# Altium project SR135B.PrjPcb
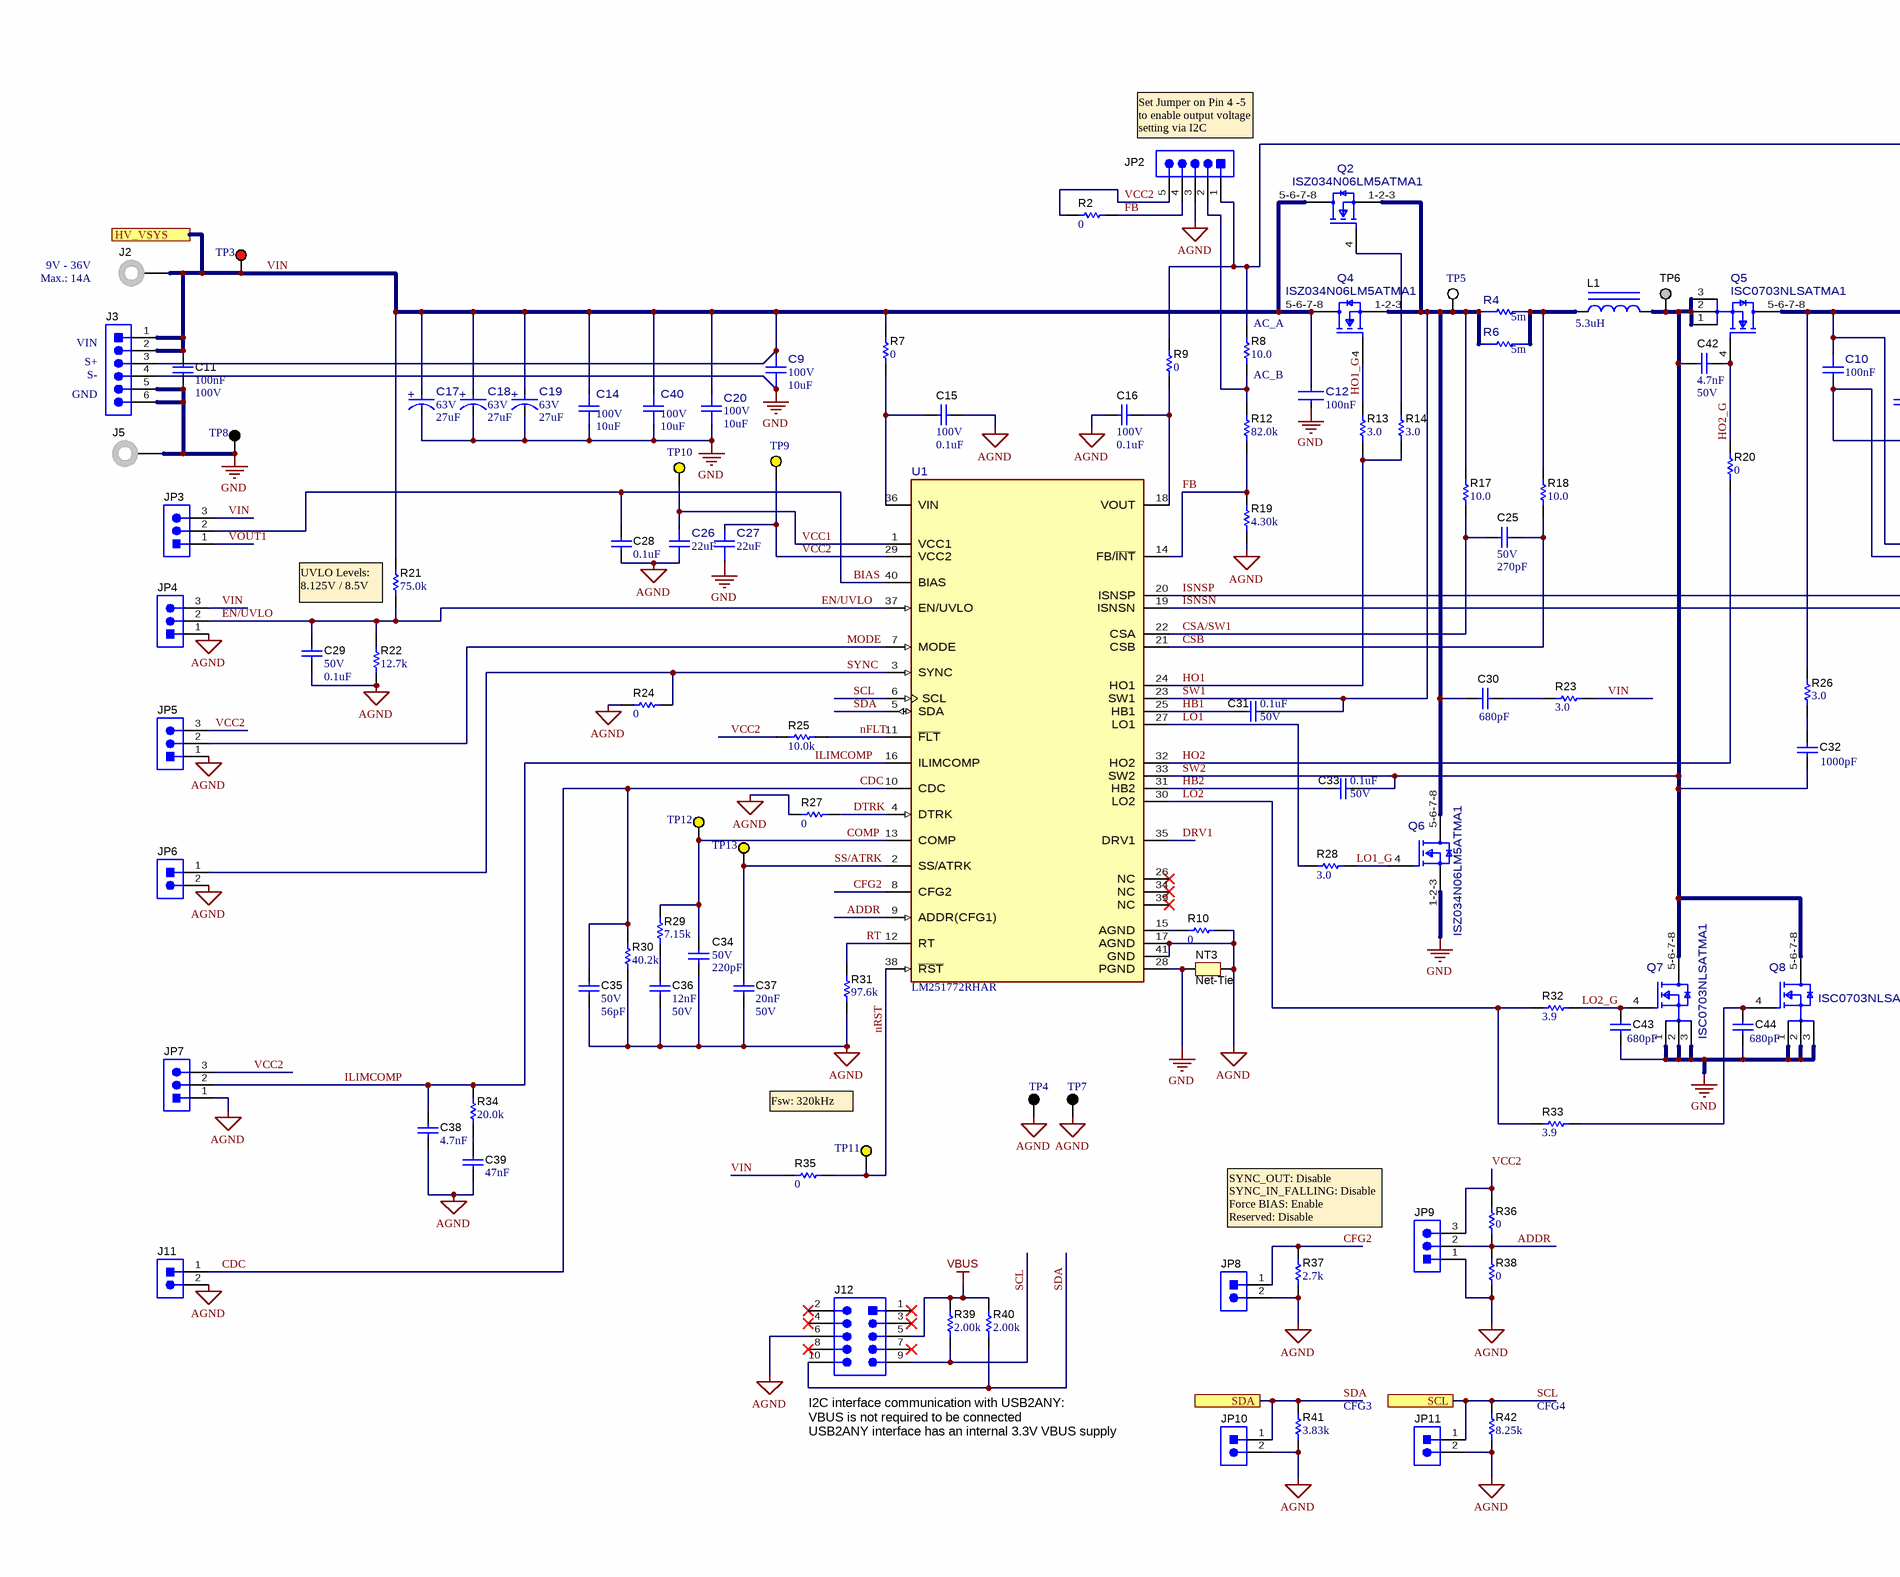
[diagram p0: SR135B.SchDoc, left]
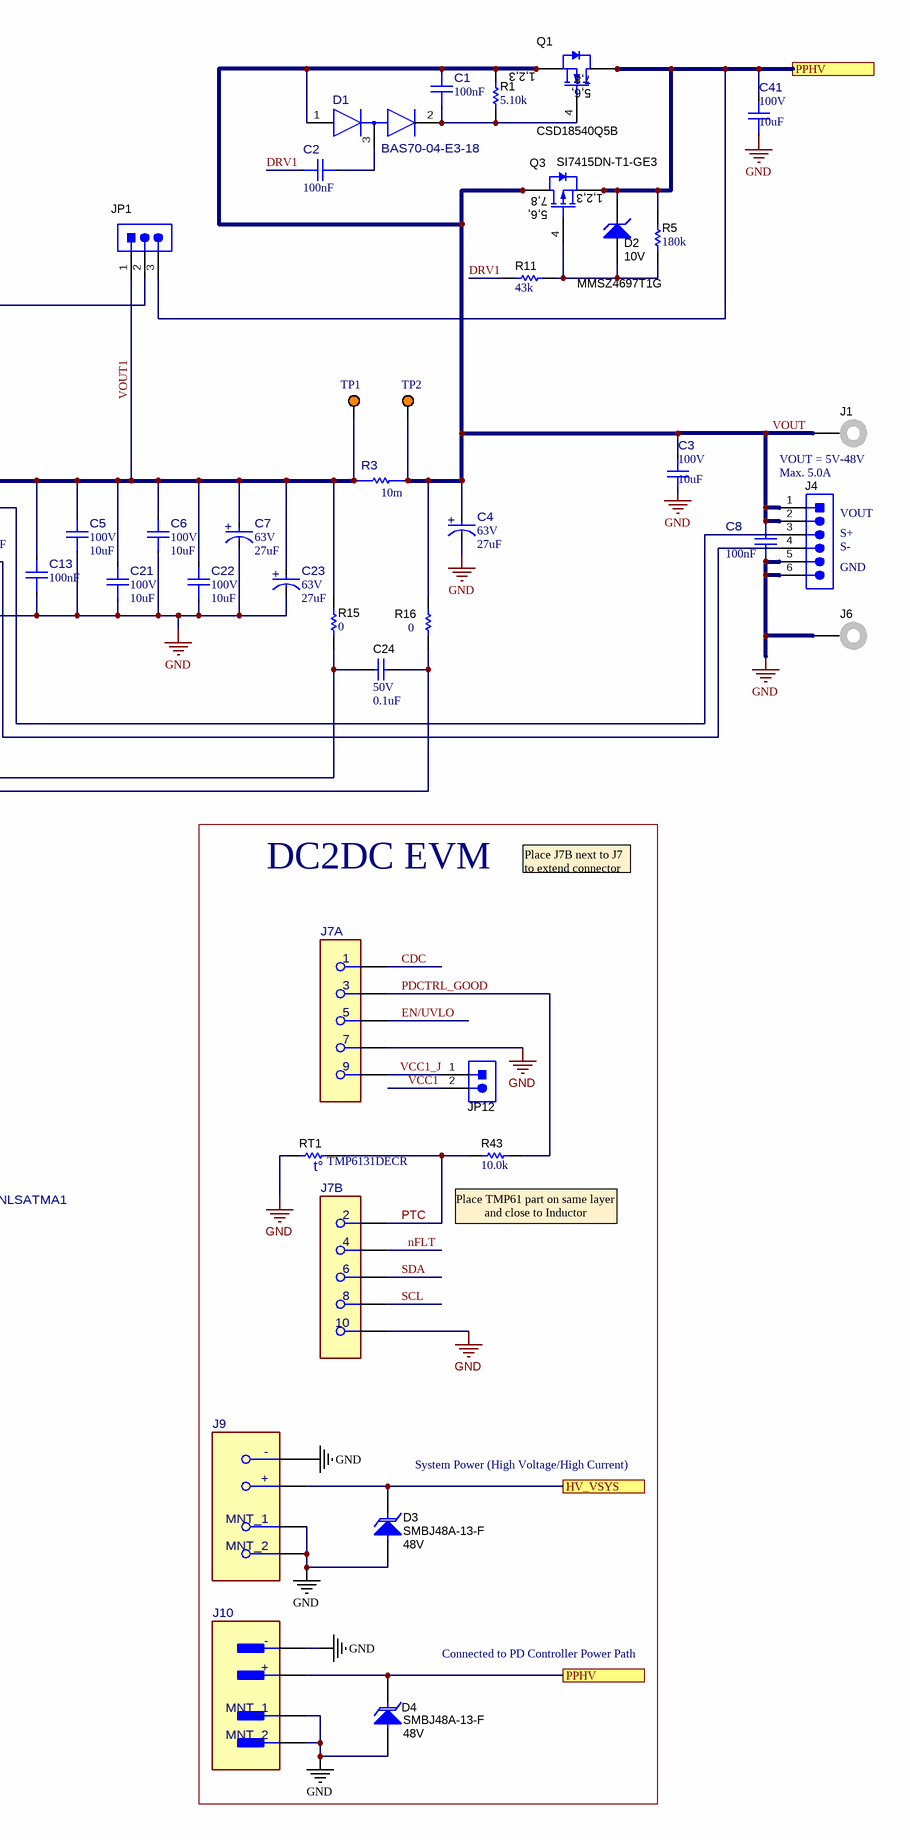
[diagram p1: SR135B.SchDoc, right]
TID: N/A; TechSupport: http://www.ti.com/support; SCH_Rev: B; PRJ_Title: LM251772EVM-PD; PRJ_Number: SR135; PRJ_Customer: Public Release; PCB_Rev: B; CopyrightYear: 2025
2 sheets, 170 parts. Net scope: flat (ports and power ports of the same name join across sheets).
Board file: SR135B.PcbDoc
Sheets:
  SR135B.SchDoc
  SR135B_Hardware.SchDoc

## Sheet SR135B.SchDoc
size 558 x 431 mm; Date: Not shown in title block; ApprovedBy: Not shown in title block; CheckedBy: Not shown in title block; Author: Not shown in title block; CompanyName: Not shown in title block; Engineer: Not shown in title block; Organization: Not shown in title block; Address1: Not shown in title block; Address2: Not shown in title block; Address3: Not shown in title block; Address4: Not shown in title block; DocumentNumber: 1; Revision: Use project parameter SCH_Rev; SheetNumber: 1; SheetTotal: 2; PageSetup: Record=PageOptions¦CenterHorizontal=True¦CenterVertical=True¦PrintScale=1.00¦XCorrection=1.00¦YCorrection=1.00¦PrintKind=0¦BorderSize=5000000¦LeftOffset=0¦BottomOffset=0¦Orientation=2¦PaperLength=1000¦PaperWidth=1000¦Scale=100¦PaperSource=15¦PrintQuality=600¦MediaType=1¦DitherType=10¦PaperKind=Letter¦PrintScaleMode=1

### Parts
C1  Cap_F: 100nF  [FP-GRM188R72A104KA35D_0603-MFG]  (hidden comment: GRM188R72A104KA35D)
C2  Cap_F: 100nF  [FP-GRM188R72A104KA35D_0603-MFG]  (hidden comment: GRM188R72A104KA35D)
C3  VDC_V: 100V  ValueDisplayed: 10uF  [FP-C3225X7R2A106K250AC_1210-MFG]  (hidden comment: C3225X7R2A106K250AC)
C4  VDC_V: 63V  ValueDisplayed: 27uF  [FP-A768KE276M1JLAE054_SMT_CAP_8MM3_8MM3-0]  (hidden comment: A768KE276M1JLAE054)
C5  VDC_V: 100V  ValueDisplayed: 10uF  [FP-C3225X7R2A106K250AC_1210-MFG]  (hidden comment: C3225X7R2A106K250AC)
C6  VDC_V: 100V  ValueDisplayed: 10uF  [FP-C3225X7R2A106K250AC_1210-MFG]  (hidden comment: C3225X7R2A106K250AC)
C7  VDC_V: 63V  ValueDisplayed: 27uF  [FP-A768KE276M1JLAE054_SMT_CAP_8MM3_8MM3-0]  (hidden comment: A768KE276M1JLAE054)
C8  Cap_F: 100nF  [FP-GRM188R72A104KA35D_0603-MFG]  (hidden comment: GRM188R72A104KA35D)
C9  VDC_V: 100V  ValueDisplayed: 10uF  [FP-C3225X7R2A106K250AC_1210-MFG]  (hidden comment: C3225X7R2A106K250AC)
C10  Cap_F: 100nF  [FP-GRM188R72A104KA35D_0603-MFG]  (hidden comment: GRM188R72A104KA35D)
C11  Cap_F: 100nF  VDC_V: 100V  [0603]  (hidden comment: GCJ188R72A104KA01D)
C12  Cap_F: 100nF  [FP-GCM188L81H104KA57D_0603-MFG]  (hidden comment: GCM188L81H104KA57D)
C13  Cap_F: 100nF  [FP-GRM188R72A104KA35D_0603-MFG]  (hidden comment: GRM188R72A104KA35D)
C14  VDC_V: 100V  ValueDisplayed: 10uF  [FP-C3225X7R2A106K250AC_1210-MFG]  (hidden comment: C3225X7R2A106K250AC)
C15  VDC_V: 100V  ValueDisplayed: 0.1uF  [0402S]  (hidden comment: GRM155R62A104KE14D)
C16  VDC_V: 100V  ValueDisplayed: 0.1uF  [0402S]  (hidden comment: GRM155R62A104KE14D)
C17  VDC_V: 63V  ValueDisplayed: 27uF  [FP-A768KE276M1JLAE054_SMT_CAP_8MM3_8MM3-0]  (hidden comment: A768KE276M1JLAE054)
C18  VDC_V: 63V  ValueDisplayed: 27uF  [FP-A768KE276M1JLAE054_SMT_CAP_8MM3_8MM3-0]  (hidden comment: A768KE276M1JLAE054)
C19  VDC_V: 63V  ValueDisplayed: 27uF  [FP-A768KE276M1JLAE054_SMT_CAP_8MM3_8MM3-0]  (hidden comment: A768KE276M1JLAE054)
C20  VDC_V: 100V  ValueDisplayed: 10uF  [FP-C3225X7R2A106K250AC_1210-MFG]  (hidden comment: C3225X7R2A106K250AC)
C21  VDC_V: 100V  ValueDisplayed: 10uF  [FP-C3225X7R2A106K250AC_1210-MFG]  (hidden comment: C3225X7R2A106K250AC)
C22  VDC_V: 100V  ValueDisplayed: 10uF  [FP-C3225X7R2A106K250AC_1210-MFG]  (hidden comment: C3225X7R2A106K250AC)
C23  VDC_V: 63V  ValueDisplayed: 27uF  [FP-A768KE276M1JLAE054_SMT_CAP_8MM3_8MM3-0]  (hidden comment: A768KE276M1JLAE054)
C24  VDC_V: 50V  ValueDisplayed: 0.1uF  [0402S]  (hidden comment: GRM155R71H104ME14D)
C25  VDC_V: 50V  ValueDisplayed: 270pF  [0402S]  (hidden comment: GRM1555C1H271JA01D)
C26  ValueDisplayed: 22uF  [0603S]  (hidden comment: GRT188R61A226ME13D)
C27  ValueDisplayed: 22uF  [0603S]  (hidden comment: GRT188R61A226ME13D)
C28  ValueDisplayed: 0.1uF  [0603S]  (hidden comment: CGA3E3X7S2A104K080AB)
C29  VDC_V: 50V  ValueDisplayed: 0.1uF  [0402S]  (hidden comment: GRM155R71H104ME14D)
C30  ValueDisplayed: 680pF  [0805_HV1]  (hidden comment: 08051A681JAT2A)
C31  VDC_V: 50V  ValueDisplayed: 0.1uF  [0402S]  (hidden comment: GCM155R71H104KE02D)
C32  ValueDisplayed: 1000pF  [0805_HV1]  (hidden comment: C0805C102J1GACTU)
C33  VDC_V: 50V  ValueDisplayed: 0.1uF  [0402S]  (hidden comment: GCM155R71H104KE02D)
C34  VDC_V: 50V  ValueDisplayed: 220pF  [0603S]  (hidden comment: 06035A221FAT2A)
C35  VDC_V: 50V  ValueDisplayed: 56pF  [0603S]  (hidden comment: 06035A560FAT2A)
C36  Cap_F: 12nF  VDC_V: 50V  [0603S]  (hidden comment: C0603C123K5RACTU)
C37  Cap_F: 20nF  VDC_V: 50V  [0603S]  (hidden comment: CC0603KRX7R9BB203)
C38  Cap_F: 4.7nF  [0603S]  (hidden comment: 06031C472JAT2A)
C39  Cap_F: 47nF  [0603S]  (hidden comment: 06035C473JAT2A)
C40  VDC_V: 100V  ValueDisplayed: 10uF  [FP-C3225X7R2A106K250AC_1210-MFG]  (hidden comment: C3225X7R2A106K250AC)
C41  VDC_V: 100V  ValueDisplayed: 10uF  [FP-C3225X7R2A106K250AC_1210-MFG]  (hidden comment: C3225X7R2A106K250AC)
C42  Cap_F: 4.7nF  VDC_V: 50V  [0603S]  (hidden comment: C0603C472K5RACTU)
C43  ValueDisplayed: 680pF  [0603S]  (hidden comment: C0603C681J5GACTU)
C44  ValueDisplayed: 680pF  [0603S]  (hidden comment: C0603C681J5GACTU)
D1  BAS70-04-E3-18  [FP-BAS70-04-E3-18_SOT23-3-MFG]
D2  MMSZ4697T1G  value 10V  [SOD-123]
D3  SMBJ48A-13-F  value 48V  [SMB]
D4  SMBJ48A-13-F  value 48V  [SMB]
J1  108-0740-001  [Johnson_108-0740-001]  (value not drawn)
J2  108-0740-001  [Johnson_108-0740-001]  (value not drawn)
J3  61300611121  [WURTH_61300611121]  (value not drawn)
J4  61300611121  [WURTH_61300611121]  (value not drawn)
J5  108-0740-001  [Johnson_108-0740-001]  (value not drawn)
J6  108-0740-001  [Johnson_108-0740-001]  (value not drawn)
J7  SSW-105-02-G-D-RA  [FP-SSW-105-02-G-D-RA_HDR10-MFG]  (value not drawn)  (parts A,B of 2)
J9  XT30PW-F  [FP-XT30PW-F_CONN_SOCKET_DC2-MFG]  (value not drawn)
J10  XT30PW-M  [FP-XT30PW-M_CONN_PLUG2-MFG]  (value not drawn)
J11  61300211121  [WURTH_61300211121]  (value not drawn)
J12  N2510-6002-RB  [CONN_2510-6002]  (value not drawn)
JP1  61300311121  [WURTH_61300311121]  (value not drawn)
JP2  61300511121  [Wurth_61300511121]  (value not drawn)
JP3  61300311121  [WURTH_61300311121]  (value not drawn)
JP4  61300311121  [WURTH_61300311121]  (value not drawn)
JP5  61300311121  [WURTH_61300311121]  (value not drawn)
JP6  61300211121  [WURTH_61300211121]  (value not drawn)
JP7  61300311121  [WURTH_61300311121]  (value not drawn)
JP8  61300211121  [WURTH_61300211121]  (value not drawn)
JP9  61300311121  [WURTH_61300311121]  (value not drawn)
JP10  61300211121  [WURTH_61300211121]  (value not drawn)
JP11  61300211121  [WURTH_61300211121]  (value not drawn)
JP12  61300211121  [WURTH_61300211121]  (value not drawn)
L1  ValueDisplayed: 5.3uH  [XAL1580]  (hidden comment: XAL1580-532MEB)
NT3  Net-Tie  [Net-Tie_10mil]  (net tie, no BOM)
Q1  CSD18540Q5B  [DNK0008A]
Q2  ISZ034N06LM5ATMA1  [FP-ISZ034N06LM5ATMA1_TSDSON8-MFG]
Q3  SI7415DN-T1-GE3  [PowerPAK_1212-8]
Q4  ISZ034N06LM5ATMA1  [FP-ISZ034N06LM5ATMA1_TSDSON8-MFG]
Q5  ISC0703NLSATMA1  [FP-ISC0702NLSATMA1_SuperSO8-5x6-MFG]
Q6  ISZ034N06LM5ATMA1  [FP-ISZ034N06LM5ATMA1_TSDSON8-MFG]
Q7  ISC0703NLSATMA1  [FP-ISC0702NLSATMA1_SuperSO8-5x6-MFG]
Q8  ISC0703NLSATMA1  [FP-ISC0702NLSATMA1_SuperSO8-5x6-MFG]
R1  ValueDisplayed: 5.10k  [0603S]  (hidden comment: RC0603FR-075K1L)
R2  ValueDisplayed: 0  [0603S]  (hidden comment: RMCF0603ZT0R00)
R3  value 10m  [FP-KRL2012E-C-R010-F-T05_0508-MFG]  (hidden comment: KRL2012E-C-R010-F-T05)
R4  value 5m  [FP-KRL2012E-M-R005-F-T5_0805_WIDE-MFG]  (hidden comment: KRL2012E-M-R005-F-T5)
R5  ValueDisplayed: 180k  [0603S]  (hidden comment: CRCW0603180KJNEA)
R6  value 5m  [FP-KRL2012E-M-R005-F-T5_0805_WIDE-MFG]  (hidden comment: KRL2012E-M-R005-F-T5)
R7  ValueDisplayed: 0  [0603S]  (hidden comment: RMCF0603ZT0R00)
R8  ValueDisplayed: 10.0  [0603S]  (hidden comment: RC0603FR-0710RL)
R9  ValueDisplayed: 0  [0603S]  (hidden comment: RMCF0603ZT0R00)
R10  ValueDisplayed: 0  [0603S]  (hidden comment: RMCF0603ZT0R00)
R11  ValueDisplayed: 43k  [0603S]  (hidden comment: CRCW060343K0JNEA)
R12  ValueDisplayed: 82.0k  [0603S]  (hidden comment: RC0603FR-0782KL)
R13  ValueDisplayed: 3.0  [0603S]  (hidden comment: CRCW06033R00JNEA)
R14  ValueDisplayed: 3.0  [0603S]  (hidden comment: CRCW06033R00JNEA)
R15  ValueDisplayed: 0  [0603S]  (hidden comment: RMCF0603ZT0R00)
R16  ValueDisplayed: 0  [0603S]  (hidden comment: RMCF0603ZT0R00)
R17  ValueDisplayed: 10.0  [0603S]  (hidden comment: CRCW060310R0FKEAHP)
R18  ValueDisplayed: 10.0  [0603S]  (hidden comment: CRCW060310R0FKEAHP)
R19  ValueDisplayed: 4.30k  [0603S]  (hidden comment: RC0603FR-074K3L)
R20  ValueDisplayed: 0  [0603S]  (hidden comment: RMCF0603ZT0R00)
R21  ValueDisplayed: 75.0k  [0603S]  (hidden comment: RC0603FR-0775KL)
R22  ValueDisplayed: 12.7k  [0603S]  (hidden comment: RC0603FR-0712K7L)
R23  ValueDisplayed: 3.0  [1206L]  (hidden comment: CRCW12063R00JNEA)
R24  ValueDisplayed: 0  [0603S]  (hidden comment: RMCF0603ZT0R00)
R25  ValueDisplayed: 10.0k  [0603S]  (hidden comment: RT0603BRD0710KL)
R26  ValueDisplayed: 3.0  [1206L]  (hidden comment: CRCW12063R00JNEA)
R27  ValueDisplayed: 0  [0603S]  (hidden comment: RMCF0603ZT0R00)
R28  ValueDisplayed: 3.0  [0603S]  (hidden comment: CRCW06033R00JNEA)
R29  ValueDisplayed: 7.15k  [0603S]  (hidden comment: CRCW06037K15FKEA)
R30  ValueDisplayed: 40.2k  [0603S]  (hidden comment: CRCW060340K2FKEA)
R31  ValueDisplayed: 97.6k  [0603S]  (hidden comment: RC0603FR-0797K6L)
R32  ValueDisplayed: 3.9  [0603S]  (hidden comment: CRCW06033R90JNEA)
R33  ValueDisplayed: 3.9  [0603S]  (hidden comment: CRCW06033R90JNEA)
R34  ValueDisplayed: 20.0k  [0603S]  (hidden comment: CRCW060320K0FKEA)
R35  ValueDisplayed: 0  [0603S]  (hidden comment: RMCF0603ZT0R00)
R36  ValueDisplayed: 0  [0603S]  (hidden comment: RMCF0603ZT0R00)
R37  ValueDisplayed: 2.7k  [0603S]  (hidden comment: CRCW06032K70JNEA)
R38  ValueDisplayed: 0  [0603S]  (hidden comment: RMCF0603ZT0R00)
R39  ValueDisplayed: 2.00k  [0603S]  (hidden comment: RC0603FR-072KL)
R40  ValueDisplayed: 2.00k  [0603S]  (hidden comment: RC0603FR-072KL)
R41  ValueDisplayed: 3.83k  [0603S]  (hidden comment: CRCW06033K83FKEA)
R42  ValueDisplayed: 8.25k  [0603S]  (hidden comment: RC0603FR-078K25L)
R43  ValueDisplayed: 10.0k  [TNPW0603]  (hidden comment: TNPW060310K0BEEA)
RT1  TMP6131DECR  [DEC0002A-MFG]
TP1  5013  [Keystone5013]  (value not drawn)
TP2  5013  [Keystone5013]  (value not drawn)
TP3  5010  [Keystone5010]  (value not drawn)
TP4  5001  [Keystone5001]  (value not drawn)
TP5  5012  [Keystone5012]  (value not drawn)
TP6  5128  [Keystone5128]  (value not drawn)
TP7  5001  [Keystone5001]  (value not drawn)
TP8  5011  [Keystone5011]  (value not drawn)
TP9  5004  [Keystone5004]  (value not drawn)
TP10  5004  [Keystone5004]  (value not drawn)
TP11  5004  [Keystone5004]  (value not drawn)
TP12  5004  [Keystone5004]  (value not drawn)
TP13  5004  [Keystone5004]  (value not drawn)
U1  LM251772RHAR  [RHA0040P-MFG]

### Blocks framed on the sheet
DC2DC EVM: D3 D4 J7 J9 J10 JP12 R43 RT1

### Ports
HV_VSYS, PPHV, SCL, SDA

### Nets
AGND: C15.1 C16.2 C26.1 C28.1 C29.2 C34.2 C35.2 C36.2 C37.2 C38.2 C39.2 J11.2 J12.6 JP2.3 JP4.1 JP5.1 JP6.2 JP7.1 JP8.2 JP9.1 JP10.2 JP11.2 NT3.2 R10.1 R19.1 R22.1 R24.1 R27.1 R30.1 R31.1 R37.1 R38.2 R41.1 R42.1 TP4.1 TP7.1 U1.17(AGND) U1.41(GND)
GND: C3.1 C4.1(CATHODE) C5.1 C6.1 C7.1(CATHODE) C8.1 C9.1 C10.1 C11.2 C12.2 C13.1 C14.1 C17.1(CATHODE) C18.1(CATHODE) C19.1(CATHODE) C20.1 C21.1 C22.1 C23.1(CATHODE) C27.1 C40.1 C41.1 C43.2 C44.2 D3.2(A) D4.2(A) J3.4 J3.5 J3.6 J4.4 J4.5 J4.6 J5.1 J6.1 J7.7 J7.10 J9.1(-) J9.3(MNT_1) J9.4(MNT_2) J10.1(-) J10.3(MNT_1) J10.4(MNT_2) NT3.1 Q6.1-2-3(S) Q7.1(Source) Q7.2(Source) Q7.3(Source) Q8.1(Source) Q8.2(Source) Q8.3(Source) RT1.1 TP8.1 U1.28(PGND)
VBUS: J12.5 R39.2 R40.2
ADDR: JP9.2 R36.2 R38.1 U1.9(ADDR(CFG1))
BIAS: C28.2 JP3.2 U1.40(BIAS)
CDC: C35.1 J7.1 J11.1 R30.2 U1.10(CDC)
CFG2: JP8.1 R37.2 U1.8(CFG2)
COMP: C34.1 R29.2 TP12.1 U1.13(COMP)
CSA/SW1: C25.2 R17.1 U1.22(CSA)
CSB: C25.1 R18.1 U1.21(CSB)
DRV1: C2.1 R11.1 U1.35(DRV1)
DTRK: R27.2 U1.4(DTRK)
EN/UVLO: C29.1 J7.5 JP4.2 R21.1 R22.2 U1.37(EN/UVLO)
FB: JP2.4 R2.1 R12.1 R19.2 U1.14(FB/~{INT})
HB1: C31.2 U1.25(HB1)
HB2: C33.2 U1.31(HB2)
HO1: R13.1 R14.1 U1.24(HO1)
HO1_G: Q4.4(G) R13.2
HO2: R20.1 U1.32(HO2)
HO2_G: C42.2 Q5.4(Gate) R20.2
ILIMCOMP: C38.1 JP7.2 R34.2 U1.16(ILIMCOMP)
ISNSN: C24.1 R16.1 U1.19(ISNSN)
ISNSP: C24.2 R15.1 U1.20(ISNSP)
LO1: R28.2 U1.27(LO1)
LO1_G: Q6.4(G) R28.1
LO2: R32.1 R33.1 U1.30(LO2)
LO2_G: C43.1 Q7.4(Gate) R32.2
MODE: JP5.2 U1.7(MODE)
nFLT: J7.4 R25.1 U1.11(~{FLT})
nRST: R35.1 TP11.1 U1.38(~{RST})
PDCTRL_GOOD: J7.3 R43.1
PPHV: C41.2 D2.1(K) D4.1(K) J10.2(+) JP1.3 Q1.5(D) Q1.6(D) Q1.7(D) Q1.8(D) Q1.9(D) Q3.1(S) Q3.2(S) Q3.3(S) R5.2 ; port PPHV
PTC: J7.2 R43.2 RT1.2
RT: R31.2 U1.12(RT)
SCL: J7.8 J12.9 JP11.1 R39.1 R42.2 U1.6(SCL) ; port SCL
SDA: J7.6 J12.10 JP10.1 R40.1 R41.2 U1.5(SDA) ; port SDA
SS/ATRK: C37.1 TP13.1 U1.2(SS/ATRK)
SW1: C30.2 C31.1 Q2.1-2-3(S) Q4.1-2-3(S) Q6.5-6-7-8(D) R4.2 R6.2 R17.2 TP5.1 U1.23(SW1)
SW2: C32.2 C33.1 C42.1 L1.2 Q5.1(Source) Q5.2(Source) Q5.3(Source) Q7.5-6-7-8(Drain) Q8.5-6-7-8(Drain) TP6.1 U1.33(SW2)
SYNC: JP6.1 R24.2 U1.3(SYNC)
VCC1: C26.2 JP12.2 TP10.1 U1.1(VCC1)
VCC1_J: J7.9 JP12.1
VCC2: C27.2 JP2.5 JP5.3 JP7.3 JP9.3 R2.2 R25.2 R36.1 TP9.1 U1.29(VCC2)
VIN: C9.2 C11.1 C12.1 C14.2 C17.2(ANODE) C18.2(ANODE) C19.2(ANODE) C20.2 C40.2 D3.1(K) J2.1 J3.1 J3.2 J3.3 J9.2(+) JP3.3 JP4.3 Q2.5-6-7-8(D) Q4.5-6-7-8(D) R7.2 R21.2 R23.2 R35.2 TP3.1 ; port HV_VSYS
VOUT: C1.2 C3.2 C4.2(ANODE) C8.2 D1.1(1_ANODE) J1.1 J4.1 J4.2 Q1.1(S) Q1.2(S) Q1.3(S) Q3.5(D) Q3.6(D) Q3.7(D) Q3.8(D) Q3.9(D) R1.2 R3.2 R16.2 TP2.1
VOUT1: C5.2 C6.2 C7.2(ANODE) C10.2 C13.2 C21.2 C22.2 C23.2(ANODE) J4.3 JP1.1 JP3.1 Q5.5-6-7-8(Drain) R3.1 R15.2 R26.2 TP1.1
NetC1_1: C1.1 D1.2(2_CATHODE) Q1.4(G) R1.1
NetC2_2: C2.2 D1.3(1_CATHODE/2_ANODE)
NetC15_2: C15.2 R7.1 U1.36(VIN)
NetC16_1: C16.1 R9.1 U1.18(VOUT)
NetC30_1: C30.1 R23.1
NetC32_1: C32.1 R26.1
NetC36_1: C36.1 R29.1
NetC39_1: C39.1 R34.1
NetC44_1: C44.1 Q8.4(Gate) R33.2
NetD2_2: D2.2(A) Q3.4(G) R5.1 R11.2
NetJP1_2: JP1.2 JP2.1 R8.2 R9.2
NetJP2_2: JP2.2 R8.1 R12.2
NetL1_1: L1.1 R4.1 R6.1 R18.2
NetQ2_4: Q2.4(G) R14.2
NetR10_2: R10.2 U1.15(AGND)

Not connected (* = marked no-connect by the designer): J12 1* 2* 3* 4* 7* 8*; U1 26(NC)* 34(NC)* 39(NC)*

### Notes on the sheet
- (near JP2) Set Jumper on Pin 4 -5 to enable output voltage setting via I2C
- 9V - 36V
- Max.: 14A
- (near J3) VIN
- (near R8) AC_A
- (near J1) VOUT = 5V-48V
- Max. 5.0A
- (near J4) VOUT
- (near J3) S+
- (near J3) S-
- (near J3) GND
- (near R8) AC_B
- (near J4) S+
- (near J4) S-
- (near J4) GND
- (near R21) UVLO Levels:
  8.125V / 8.5V
- Place J7B next to J7 to extend connector
- (near R43) Place TMP61 part on same layer and close to Inductor
- Fsw: 320kHz
- (near R37) SYNC_OUT: Disable
  SYNC_IN_FALLING: Disable
  Force BIAS: Enable
  Reserved: Disable
- (near D3) System Power (High Voltage/High Current)
- (near R41) CFG3
- (near R42) CFG4
- Connected to PD Controller Power Path
- (near J12) I2C interface communication with USB2ANY:
  VBUS is not required to be connected
  USB2ANY interface has an internal 3.3V VBUS supply

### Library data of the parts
C1 C2 C8 C10 C13 = CMP-0088837-1: 0.1µF ±10% 100V Ceramic Capacitor X7R 0603 (1608 Metric); Manufacturer: Murata; AEC Qualified: No; Import Ts: 1521862704; TempCo: 15%; Ciiva Ids: 120189; ValueDisplayed: 0.1uF; SizeZ_mm: 0.9mm
C3 C5 C6 C9 C14 C20-C22 C40 C41 = CMP-0096021-1: 10 µF ±10% 100V Ceramic Capacitor X7R 1210 (3225 Metric); Manufacturer: TDK; Cap_F: 10µF; AEC Qualified: No; Value: 10µF; SizeZ_mm: 2.85mm; TempCo: 15%
C4 C7 C17-C19 C23 = CMP-0097690-1: Cap Aluminum Polymer 27uF 63V 20% Solder Cylindrical 54m Ohm 1175mA 2000 hr 125°C T/R; Manufacturer: KEMET; Life: 2000Hours; Cap_F: 27µF; Value: 27µF; Leakage Current: 340uA; SizeZ_mm: 7mm; IRMS_A: 1.175A; AEC Qualified: No
C11 = CMP-0064935-4: CAP, CERM, 0.1 uF, 100 V,+/- 10%, X7R, AEC-Q200 Grade 1, 0603; Manufacturer: MuRata; TaMin_C: -55°C; Polarized: N; SizeAreaWB_mm2: 4.68; Value1: Unknown; U/M: EA; Value: 0.1uF; TaMax_C: 125°C; SizeZ_mm: 1; SizeX_mm: 1.6; SizeY_mm: 0.8; SizeArea_mm2: 1.28; AEC Qualified: Y; AEC Category: Q200
C12 = CMP-0086535-1: 0.1µF ±10% 50V Ceramic Capacitor X8L 0603 (1608 Metric); Manufacturer: Murata Electronics North America; Symbol Name: SYM-GCM188L81H104KA57D; AEC Qualified: Yes; TempCo: -40+15%; SizeZ_mm: 0.9mm; AEC Grade: Grade 0
C15 C16 = CMP-0006618-2: CAP, CERM, 0.1 uF, 100 V, +/- 10%, X5R, 0402; Manufacturer: MuRata; TaMin_C: -55°C; Polarized: N; SizeAreaWB_mm2: 3; Value1: Unknown; U/M: EA; Value: 0.1uF; TaMax_C: 85°C; SizeZ_mm: 0.6; SizeX_mm: 1; SizeY_mm: 0.5; Cap_Case: 0402; Cap_F: 100nF; AEC Category: Q200
C24 C29 = CMP-0006675-2: CAP, CERM, 0.1 uF, 50 V, +/- 20%, X7R, 0402; Manufacturer: MuRata; TaMin_C: -55°C; Polarized: N; SizeAreaWB_mm2: 3; Value1: Unknown; U/M: EA; Value: 0.1uF; TaMax_C: 125°C; SizeZ_mm: 0.6; SizeX_mm: 1; SizeY_mm: 0.5; Cap_Case: 0402; Cap_F: 100nF; AEC Category: Q200
C25 = CMP-0006445-2: CAP, CERM, 270 pF, 50 V, +/- 5%, C0G/NP0, 0402; Manufacturer: MuRata; TaMin_C: -55°C; Polarized: N; SizeAreaWB_mm2: 3; Value1: Unknown; U/M: EA; Value: 270pF; TaMax_C: 125°C; SizeZ_mm: 0.6; SizeX_mm: 1; SizeY_mm: 0.5; Cap_Case: 0402; AEC Category: Q200
C26 C27 = CMP-0092433-2: Multi-Layer Ceramic Capacitor 22uF 10V X5R ±20% 0603 Paper T/R; Manufacturer: Murata; Cap_F: 22µF; Value: 22µF; SizeZ_mm: 1mm; AEC Qualified: Yes; AEC Grade: Grade 3; TempCo: 15%
C28 = CMP-0007099-4: CAP, CERM, 0.1 uF, 100 V, +/- 10%, X7S, AEC-Q200 Grade 1, 0603; Manufacturer: TDK; TaMin_C: -55°C; ESR_ohm: 0.04959; Polarized: N; SizeAreaWB_mm2: 4.68; Value1: 0.04959 ohm; U/M: EA; Value: 0.1uF; TaMax_C: 125°C; SizeZ_mm: 1; SizeX_mm: 1.6; SizeY_mm: 0.8; Cap_Case: 0603; Value2: 100V; SizeArea_mm2: 1.28; AEC Qualified: Y; Cap_F: 100nF; IRMS_A: 7.51618dA; AEC Category: Q200
C30 = CMP-0007537-2: CAP, CERM, 680 pF, 100 V, +/- 5%, C0G/NP0, 0805; Manufacturer: AVX; TaMin_C: -55°C; ESR_ohm: 1.34d; Polarized: N; SizeAreaWB_mm2: 6.75; Value1: 0.134 ohm; U/M: EA; Value: 680pF; TaMax_C: 125°C; SizeZ_mm: 1.45; SizeX_mm: 2; SizeY_mm: 1.25; Cap_Case: 0805; Value2: 100V; SizeArea_mm2: 2.5; AEC Category: Q200
C31 C33 = CMP-0006356-2: CAP, CERM, 0.1 uF, 50 V, +/- 10%, X7R, AEC-Q200 Grade 1, 0402; Manufacturer: MuRata; TaMin_C: -55°C; Polarized: N; SizeAreaWB_mm2: 3; Value1: Unknown; U/M: EA; Value: 0.1uF; TaMax_C: 125°C; SizeZ_mm: 0.6; SizeX_mm: 1; SizeY_mm: 0.5; Cap_Case: 0402; AEC Qualified: Y; Cap_F: 100nF; AEC Category: Q200
C32 = CMP-0007709-2: CAP, CERM, 1000 pF, 100 V, +/- 5%, C0G/NP0, 0805; Manufacturer: Kemet; TaMin_C: -55°C; ESR_ohm: 0.025; Polarized: N; SizeAreaWB_mm2: 6.75; Value1: 0.025 ohm; U/M: EA; Value: 1000pF; TaMax_C: 125°C; SizeZ_mm: 1.45; SizeX_mm: 2; SizeY_mm: 1.25; Cap_Case: 0805; Value2: 100V; SizeArea_mm2: 2.5; Cap_F: 1nF; IRMS_A: 1.71A; AEC Category: Q200
C34 = CMP-0006776-4: CAP, CERM, 220 pF, 50 V, +/- 1%, C0G/NP0, 0603; Manufacturer: AVX; TaMin_C: -55°C; ESR_ohm: 83m; Polarized: N; SizeAreaWB_mm2: 4.68; Value1: 0.083 ohm; U/M: EA; Value: 220pF; TaMax_C: 125°C; SizeZ_mm: 1; SizeX_mm: 1.6; SizeY_mm: 0.8; Cap_Case: 0603; SizeArea_mm2: 1.28; AEC Category: Q200
C35 = CMP-0006792-4: CAP, CERM, 56 pF, 50 V, +/- 1%, C0G/NP0, 0603; Manufacturer: AVX; TaMin_C: -55°C; Polarized: N; SizeAreaWB_mm2: 4.68; Value1: Unknown; U/M: EA; Value: 56pF; TaMax_C: 125°C; SizeZ_mm: 1; SizeX_mm: 1.6; SizeY_mm: 0.8; Cap_Case: 0603; SizeArea_mm2: 1.28; AEC Category: Q200
C36 = CMP-0084236-1: CAP, CERM, 0.012 µF, 50 V,+/- 10%, X7R, AEC-Q200 Grade 1, 0603; Manufacturer: Kemet; TaMin_C: -55°C; Polarized: N; SizeAreaWB_mm2: 4.68; U/M: EA; Value: 0.012uF; TaMax_C: 125°C; SizeZ_mm: 1; SizeX_mm: 1.6; SizeY_mm: 0.8; Cap_Case: 0603; SizeArea_mm2: 1.28; AEC Qualified: Y; AEC Category: Q200
C37 = CMP-0086295-1: CAP, CERM, 0.02 µF, 50 V,+/- 10%, X7R, 0603; Manufacturer: Yageo; SizeX_mm: 1.6; SizeAreaWB_mm2: 4.68; TaMin_C: -55°C; SizeZ_mm: 1; SizeArea_mm2: 1.28; U/M: EA; Value: 0.02uF; Polarized: N; SizeY_mm: 0.8; TaMax_C: 125°C; Cap_Case: 0603; AEC Category: Q200; ValueDisplayed: 0.02µF
C38 = CMP-0006745-4: CAP, CERM, 4700 pF, 100 V, +/- 5%, X7R, 0603; Manufacturer: AVX; TaMin_C: -55°C; ESR_ohm: 1.36d; Polarized: N; SizeAreaWB_mm2: 4.68; Value1: 0.136 ohm; U/M: EA; Value: 4700pF; TaMax_C: 125°C; SizeZ_mm: 1; SizeX_mm: 1.6; SizeY_mm: 0.8; Cap_Case: 0603; Value2: 100V; SizeArea_mm2: 1.28; AEC Category: Q200
C39 = CMP-0085252-1: CAP, CERM, 0.047 µF, 50 V,+/- 5%, X7R, 0603; Manufacturer: AVX; VDC_V: 50V; TaMax_C: 125°C; Value: 0.047uF; SizeX_mm: 1.6; SizeArea_mm2: 1.28; AEC Category: Q200; SizeY_mm: 0.8; Polarized: N; Cap_Case: 0603; SizeAreaWB_mm2: 4.68; U/M: EA; TaMin_C: -55°C; SizeZ_mm: 1
C42 = CMP-0006943-4: CAP, CERM, 4700 pF, 50 V, +/- 10%, X7R, 0603; Manufacturer: Kemet; TaMin_C: -55°C; Polarized: N; SizeAreaWB_mm2: 4.68; Value1: Unknown; U/M: EA; Value: 4700pF; TaMax_C: 125°C; SizeZ_mm: 1; SizeX_mm: 1.6; SizeY_mm: 0.8; Cap_Case: 0603; SizeArea_mm2: 1.28; AEC Category: Q200
C43 C44 = CMP-0006959-4: CAP, CERM, 680 pF, 50 V, +/- 5%, C0G/NP0, 0603; Manufacturer: Kemet; TaMin_C: -55°C; Polarized: N; SizeAreaWB_mm2: 4.68; Value1: Unknown; U/M: EA; Value: 680pF; TaMax_C: 125°C; SizeZ_mm: 1; SizeX_mm: 1.6; SizeY_mm: 0.8; Cap_Case: 0603; Value2: 50V; SizeArea_mm2: 1.28; AEC Category: Q200
D1 = CMP-0096356-1: Diode Array 1 Pair Series Connection Schottky 70 V 200mA (DC) Surface Mount TO-236-3, SC-59, SOT-23-3; Manufacturer: Vishay; ValueDisplayed: 1.5pF; Vf_V: 70V; TJmax_C: 125°C; AEC Qualified: No; Peak Reverse Current: 0.02uA; SizeZ_mm: 1.15mm; Max Surge Forward Current: 600mA
D2 = CMP-0005740-3: Diode, Zener, 10 V, 500 mW, SOD-123; Manufacturer: ON Semiconductor; SizeY_mm: 1.7; SizeX_mm: 3.85; RJA_CperW: 340; SizeAreaWB_mm2: 13.095; AEC Category: Q101; Power_W: 500mW; SizeZ_mm: 1.35; Value1: 0.5W; SizeArea_mm2: 6.545
D3 D4 = CMP-0005570-3: Diode, TVS, Uni, 48 V, 77.4 Vc, SMB; Manufacturer: Diodes Inc.; Vbr_Min: 53.3V; AEC Category: Q101; Vbr_Max: 61.3V; Ppk: 600W; SizeZ_mm: 2.6; Ipp: 7.7A; SizeY_mm: 3.81; Vc: 77.4V; SizeAreaWB_mm2: 44.156; SizeX_mm: 5.6; SizeArea_mm2: 21.336
J1 J2 J5 J6 = CMP-0055387-2: Standard Banana Jack, Uninsulated, 15A; Manufacturer: Cinch Connectivity; CNHeader: FALSE; Green_Lifecycle: Active; Green_REACh: Passed; CT: TRUE
J3 J4 = CMP-0054801-2: Header, 2.54 mm, 6x1, Gold, TH; Manufacturer: Wurth Elektronik; Cert_UL: Y; Gender: Male; Row_Count: 1; Shrouded: N; Pitch_mm: 2.54
J7 = CMP-0120964-1: 10 Position Receptacle Connector 0.100" (2.54mm) Through Hole, Right Angle Gold; Manufacturer: Samtec; ContactFinish: Gold,Nickel; Current_A: 4.7A; Row_Count: 2; Voltage_V: 655V; AEC Qualified: No; Ciiva Ids: 678828; Conn Gender: Female; Import Ts: 1521843394; Is Female: yes; SizeZ_mm: 5.08mm
J9 = CMP-0035193-3: Socket, DC supply, XT30, female, PIN: 2, on PCBs, THT, yellow, 15A; Manufacturer: Amass; ContactFinish: Gold; Voltage_V: 500V; AEC Qualified: No; Conn Orientation: Right Angle; DUT-Pitch_mm: 5mm; Is Female: yes; Standoff Height: 0.1mm
J10 = CMP-0121007-1: Socket, DC supply, XT30, male, PIN: 2, on PCBs, THT, yellow, 15A, 500V; Manufacturer: Amass; ContactFinish: Gold; AEC Qualified: No; Conn Orientation: Right Angle; DUT-Pitch_mm: 5mm; SizeZ_mm: 5.1mm; Standoff Height: 0.1mm
J11 JP6 JP8 JP10-JP12 = CMP-0054794-2: Header, 2.54 mm, 2x1, Gold, TH; Manufacturer: Wurth Elektronik; Shrouded: N; Gender: Male; Green_REACh: Passed; Pitch_mm: 2.54; Green_Lifecycle: Active; Row_Count: 1; Cert_UL: Y
J12 = CMP-0055448-2: Header (shrouded), 100mil, 5x2, High-Temperature, Gold, TH; Manufacturer: 3M; Green_Lifecycle: Active; Green_REACh: Passed
JP1 JP3-JP5 JP7 JP9 = CMP-0054796-4: Header, 2.54 mm, 3x1, Gold, TH; Manufacturer: Wurth Elektronik; Green_Lifecycle: Active; Green_REACh: Passed; CT: FALSE; CNHeader: TRUE
JP2 = CMP-0084909-1: Header, 2.54mm, 5x1, Gold, TH; Manufacturer: Wurth Elektronik; Pitch_mm: 2.54; Current_A: 3A; Shrouded: N; Gender: Male; Voltage_V: 250V; Row_Count: 1
L1 = CMP-0060980-1: Inductor, Shielded, Composite, 5.3 uH, 26.5 A, 0.00435 ohm, SMD; Manufacturer: Coilcraft; Isat: 33A @ 0.7% inductance drop; Irms: 26.5A @ 40C rise; Green_Lifecycle: Not Set; SizeAreaWB_mm2: 313.04; DCR_ohm: 4.35m; Green_REACh: Incomplete; Value: 5.3uH; Imax_A: 26.5A; SizeZ_mm: 8; SizeX_mm: 15.2; SizeY_mm: 16.2; SizeArea_mm2: 246.24; Ind_H: 5.3µH; AEC Category: Q200
NT3 = CMP-0078142-6: Single point connection between nets.
Q1 = CMP-0000823-2: MOSFET, N-CH, 60 V, 100 A, DNK0008A (VSON-CLIP-8); Alternate Manufacturer: None; Manufacturer: Texas Instruments; SizeZ_mm: 1; ChType: N; Value2: 41 nC; Value1: 0.003; VdsMax_V: 60V; SizeX_mm: 6; SizeY_mm: 5; Vgs_V: 20V; Value: 60V; Rdson45_ohm: 3.3m; SizeArea_mm2: 30; AEC Category: Q101; IdsMax_A: 100A; SizeAreaWB_mm2: 56; U/M: EA; QgTyp_nC: 41
Q2 Q4 Q6 = CMP-0097450-1: N-Channel 60 V 19A (Ta), 112A (Tc) 2.5W (Ta), 83W (Tc) Surface Mount PG-TSDSON-8-26; Manufacturer: Infineon; Reverse Recovery Time: 20ns; Turn Off Delay Time: 27ns; Vgs_V: 20V; Threshold Vgs Min: 1.1V; TJmax_C: +175°C; Turn On Delay Time: 7.6ns; VdsMax_V: 1V; Pulse Drain Current: 448A; Rdson45_ohm: 2.9m; QgTyp_nC: 40nC @ 10V; Typ Forward Diode Voltage: 0.81V; Reverse Recovery Charge: 50nC; Rthja Max: 60°C/W; SizeZ_mm: 1mm; Transconductance: 80S; Threshold Vgs Max: 2.3V; Number Of Channels: 1; Input Capacitace At Vds: 2600pF @ 30V; AEC Qualified: No; Drain To Source Breakdown Voltage: 60V; ChMode: False
Q3 = CMP-0000115-4: MOSFET, P-CH, -60 V, -3.6 A, PowerPAK 1212; Manufacturer: Vishay-Siliconix; Alternate Manufacturer: None; IdsMax_A: -3.6A; ChType: P; Vgs_V: -20V; Value1: 0.1; QgTyp_nC: 15; VdsMax_V: -60V; SizeAreaWB_mm2: 18.49; SizeX_mm: 3.3; ChMode: Enhancement; SizeArea_mm2: 10.89; Value: -60V; AEC Category: Q101; SizeZ_mm: 1.04; Rdson45_ohm: 0.11; Value2: 15 nC
Q5 Q7 Q8 = CMP-0097724-1: MOSFET N-Channel 60 V 23A (Ta), 135A (Tc) 3W (Ta), 100W (Tc) Surface Mount PG-TDSON-8; Manufacturer: Infineon; QgTyp_nC: 42nC @ 10V; VdsMax_V: 1.1V; Turn Off Delay Time: 7.5ns; Transconductance: 130S; SizeZ_mm: 1mm; Turn On Delay Time: 6.5ns; Drain To Source Breakdown Voltage: 60V; Reverse Recovery Time: 43ns; Number Of N Channels: 1; Pulse Drain Current: 540A; TJmax_C: +175°C; Rthja Max: 50°C/W; Vgs_V: 20V; Typ Forward Diode Voltage: 0.85V; Threshold Vgs Max: 2.3V; Reverse Recovery Charge: 49nC; ChMode: False; Rdson45_ohm: 3m; Input Capacitace At Vds: 2700pF @ 30V; AEC Qualified: No
R1 = CMP-0023198-5: RES, 5.10 k, 1%, 0.1 W, 0603; Manufacturer: Yageo; Power_W: 100mW; TempCo: 100 ppm/C; Value_Code: 5k10; Value: 5.10k; Res_ohm: 5.1k; SizeX_mm: 1.6; SizeY_mm: 0.8; SizeZ_mm: 1; Value2: 0.1W; SizeArea_mm2: 1.28; AEC Qualified: N; VDC_V: 75V; AEC Category: Q200; SizeAreaWB_mm2: 4.68
R2 R7 R9 R10 R15 R16 R20 R24 R27 R35 R36 R38 = CMP-0023343-3: RES, 0, 1%, 0.1 W, AEC-Q200 Grade 0, 0603; Manufacturer: Stackpole Electronics Inc; Power_W: 100mW; TempCo: ppm/C; U/M: EA; Value: 0; SizeX_mm: 1.6; SizeY_mm: 0.8; SizeZ_mm: 1; Value2: 0.1W; SizeArea_mm2: 1.28; AEC Qualified: Y; AEC Category: Q200
R3 = CMP-0097451-1: 10 mOhms ±1% 1W Chip Resistor Wide 0805 (2012 Metric), 0508 Automotive AEC-Q200, Current Sense Metal Foil; Manufacturer: Susumu; SizeZ_mm: 0.7mm; AEC Grade: Grade 0; AEC Qualified: Yes; TempCo: 50ppm/°C
R4 R6 = CMP-0090651-1: 5 mOhms ±1% 1W Chip Resistor Wide 0805 (2012 Metric), 0508 Automotive AEC-Q200, Current Sense Metal Foil; Manufacturer: Susumu; TempCo: 50ppm/°C; AEC Grade: Grade 0; AEC Qualified: Yes; SizeZ_mm: 0.7mm
R5 = CMP-0025725-4: RES, 180 k, 5%, 0.1 W, AEC-Q200 Grade 0, 0603; Manufacturer: Vishay-Dale; Power_W: 100mW; TempCo: 200 ppm/C; Value: 180k; EIA_Code: E24; SizeX_mm: 1.6; SizeY_mm: 0.8; SizeZ_mm: 1; Value2: 0.1W; SizeArea_mm2: 1.28; AEC Qualified: Y; VDC_V: 75V; AEC Category: Q200; AEC Grade: 0
R8 = CMP-0022751-4: RES, 10.0, 1%, 0.1 W, 0603; Manufacturer: Yageo; Power_W: 100mW; TempCo: 100 ppm/C; Value_Code: 10R0; Value: 10.0; EIA_Code: E96; Res_ohm: 10; SizeX_mm: 1.6; SizeY_mm: 0.8; SizeZ_mm: 1; Value2: 0.1W; SizeArea_mm2: 1.28; AEC Qualified: N; VDC_V: 75V; AEC Category: Q200; SizeAreaWB_mm2: 4.68
R11 = CMP-0025810-4: RES, 43 k, 5%, 0.1 W, AEC-Q200 Grade 0, 0603; Manufacturer: Vishay-Dale; Power_W: 100mW; TempCo: 200 ppm/C; Value_Code: 43k0; Value: 43k; EIA_Code: E24; SizeX_mm: 1.6; SizeY_mm: 0.8; SizeZ_mm: 1; Value2: 0.1W; SizeArea_mm2: 1.28; AEC Qualified: Y; VDC_V: 75V; AEC Category: Q200; AEC Grade: 0
R12 = CMP-0023292-5: RES, 82.0 k, 1%, 0.1 W, 0603; Manufacturer: Yageo; Power_W: 100mW; TempCo: 100 ppm/C; Value_Code: 82k0; Value: 82.0k; Res_ohm: 82k; SizeX_mm: 1.6; SizeY_mm: 0.8; SizeZ_mm: 1; Value2: 0.1W; SizeArea_mm2: 1.28; AEC Qualified: N; VDC_V: 75V; AEC Category: Q200; SizeAreaWB_mm2: 4.68
R13 R14 R28 = CMP-0025804-4: RES, 3.0, 5%, 0.1 W, AEC-Q200 Grade 0, 0603; Manufacturer: Vishay-Dale; Power_W: 100mW; TempCo: 200 ppm/C; Value_Code: 3R00; Value: 3.0; EIA_Code: E24; Res_ohm: 3; SizeX_mm: 1.6; SizeY_mm: 0.8; SizeZ_mm: 1; Value2: 0.1W; SizeArea_mm2: 1.28; AEC Qualified: Y; VDC_V: 75V; AEC Category: Q200; AEC Grade: 0
R17 R18 = CMP-0022004-4: RES, 10.0, 1%, 0.25 W, AEC-Q200 Grade 0, 0603; Manufacturer: Vishay-Dale; Power_W: 250mW; TempCo: 100 ppm/C; Value_Code: 10R0; Value: 10.0; EIA_Code: E96; Res_ohm: 10; SizeX_mm: 1.6; SizeY_mm: 0.8; SizeZ_mm: 1; Value2: 0.25W; SizeArea_mm2: 1.28; AEC Qualified: Y; VDC_V: 75V; AEC Category: Q200; AEC Grade: 0
R19 = CMP-0023148-5: RES, 4.30 k, 1%, 0.1 W, 0603; Manufacturer: Yageo; Power_W: 100mW; TempCo: 100 ppm/C; Value_Code: 4k30; Value: 4.30k; Res_ohm: 4.3k; SizeX_mm: 1.6; SizeY_mm: 0.8; SizeZ_mm: 1; Value2: 0.1W; SizeArea_mm2: 1.28; AEC Qualified: N; VDC_V: 75V; AEC Category: Q200; SizeAreaWB_mm2: 4.68
R21 = CMP-0023267-5: RES, 75.0 k, 1%, 0.1 W, 0603; Manufacturer: Yageo; Power_W: 100mW; TempCo: 100 ppm/C; Value_Code: 75k0; Value: 75.0k; EIA_Code: E96; Res_ohm: 75k; SizeX_mm: 1.6; SizeY_mm: 0.8; SizeZ_mm: 1; Value2: 0.1W; SizeArea_mm2: 1.28; AEC Qualified: N; VDC_V: 75V; AEC Category: Q200; SizeAreaWB_mm2: 4.68
R22 = CMP-0022778-5: RES, 12.7 k, 1%, 0.1 W, 0603; Manufacturer: Yageo; Power_W: 100mW; TempCo: 100 ppm/C; Value_Code: 12k7; Value: 12.7k; EIA_Code: E96; SizeX_mm: 1.6; SizeY_mm: 0.8; SizeZ_mm: 1; Value2: 0.1W; SizeArea_mm2: 1.28; AEC Qualified: N; VDC_V: 75V; AEC Category: Q200; SizeAreaWB_mm2: 4.68
R23 R26 = CMP-0018676-3: RES, 3.0, 5%, 0.25 W, AEC-Q200 Grade 0, 1206; Manufacturer: Vishay-Dale; Power_W: 250mW; TempCo: 200 ppm/C; Value_Code: 3R00; Value: 3.0; EIA_Code: E24; Res_ohm: 3; SizeX_mm: 3.2; SizeY_mm: 1.6; SizeZ_mm: 1.35; Value2: 0.25W; SizeArea_mm2: 5.12; AEC Qualified: Y; VDC_V: 200V; AEC Category: Q200; AEC Grade: 0
R25 = CMP-0023653-3: RES, 10.0 k, 0.1%, 0.1 W, 0603; Manufacturer: Yageo America; Power_W: 100mW; TempCo: 25 ppm/C; Value_Code: 10k0; U/M: EA; Value: 10.0k; EIA_Code: E192; Res_ohm: 10k; SizeX_mm: 1.6; SizeY_mm: 0.8; SizeZ_mm: 1; Value2: 0.1W; SizeArea_mm2: 1.28; VDC_V: 75V; AEC Category: Q200
R29 = CMP-0022599-4: RES, 7.15 k, 1%, 0.1 W, AEC-Q200 Grade 0, 0603; Manufacturer: Vishay-Dale; Power_W: 100mW; TempCo: 100 ppm/C; Value_Code: 7k15; Value: 7.15k; EIA_Code: E96; SizeX_mm: 1.6; SizeY_mm: 0.8; SizeZ_mm: 1; Value2: 0.1W; SizeArea_mm2: 1.28; AEC Qualified: Y; VDC_V: 75V; AEC Category: Q200; AEC Grade: 0
R30 = CMP-0022410-4: RES, 40.2 k, 1%, 0.1 W, AEC-Q200 Grade 0, 0603; Manufacturer: Vishay-Dale; Power_W: 100mW; TempCo: 100 ppm/C; Value_Code: 40k2; Value: 40.2k; EIA_Code: E96; SizeX_mm: 1.6; SizeY_mm: 0.8; SizeZ_mm: 1; Value2: 0.1W; SizeArea_mm2: 1.28; AEC Qualified: Y; VDC_V: 75V; AEC Category: Q200; AEC Grade: 0
R31 = CMP-0023330-5: RES, 97.6 k, 1%, 0.1 W, 0603; Manufacturer: Yageo; Power_W: 100mW; TempCo: 100 ppm/C; Value_Code: 97k6; Value: 97.6k; EIA_Code: E96; SizeX_mm: 1.6; SizeY_mm: 0.8; SizeZ_mm: 1; Value2: 0.1W; SizeArea_mm2: 1.28; AEC Qualified: N; VDC_V: 75V; AEC Category: Q200; SizeAreaWB_mm2: 4.68
R32 R33 = CMP-0025807-4: RES, 3.9, 5%, 0.1 W, AEC-Q200 Grade 0, 0603; Manufacturer: Vishay-Dale; Power_W: 100mW; TempCo: 200 ppm/C; Value_Code: 3R90; Value: 3.9; EIA_Code: E24; SizeX_mm: 1.6; SizeY_mm: 0.8; SizeZ_mm: 1; Value2: 0.1W; SizeArea_mm2: 1.28; AEC Qualified: Y; VDC_V: 75V; AEC Category: Q200; AEC Grade: 0
R34 = CMP-0022204-4: RES, 20.0 k, 1%, 0.1 W, AEC-Q200 Grade 0, 0603; Manufacturer: Vishay-Dale; Power_W: 100mW; TempCo: 100 ppm/C; Value_Code: 20k0; Value: 20.0k; EIA_Code: E96; Res_ohm: 20k; SizeX_mm: 1.6; SizeY_mm: 0.8; SizeZ_mm: 1; Value2: 0.1W; SizeArea_mm2: 1.28; AEC Qualified: Y; VDC_V: 75V; AEC Category: Q200; AEC Grade: 0
R37 = CMP-0025771-4: RES, 2.7 k, 5%, 0.1 W, AEC-Q200 Grade 0, 0603; Manufacturer: Vishay-Dale; Power_W: 100mW; TempCo: 200 ppm/C; Value_Code: 2k70; Value: 2.7k; EIA_Code: E24; SizeX_mm: 1.6; SizeY_mm: 0.8; SizeZ_mm: 1; Value2: 0.1W; SizeArea_mm2: 1.28; AEC Qualified: Y; VDC_V: 75V; AEC Category: Q200; AEC Grade: 0
R39 R40 = CMP-0023000-5: RES, 2.00 k, 1%, 0.1 W, 0603; Manufacturer: Yageo; Power_W: 100mW; TempCo: 100 ppm/C; Value_Code: 2k00; Value: 2.00k; EIA_Code: E96; Res_ohm: 2k; SizeX_mm: 1.6; SizeY_mm: 0.8; SizeZ_mm: 1; Value2: 0.1W; SizeArea_mm2: 1.28; AEC Qualified: N; VDC_V: 75V; AEC Category: Q200; SizeAreaWB_mm2: 4.68
R41 = CMP-0022381-4: RES, 3.83 k, 1%, 0.1 W, AEC-Q200 Grade 0, 0603; Manufacturer: Vishay-Dale; Power_W: 100mW; TempCo: 100 ppm/C; Value_Code: 3k83; Value: 3.83k; EIA_Code: E96; SizeX_mm: 1.6; SizeY_mm: 0.8; SizeZ_mm: 1; Value2: 0.1W; SizeArea_mm2: 1.28; AEC Qualified: Y; VDC_V: 75V; AEC Category: Q200; AEC Grade: 0
R42 = CMP-0023307-5: RES, 8.25 k, 1%, 0.1 W, 0603; Manufacturer: Yageo; Power_W: 100mW; TempCo: 100 ppm/C; Value_Code: 8k25; Value: 8.25k; EIA_Code: E96; SizeX_mm: 1.6; SizeY_mm: 0.8; SizeZ_mm: 1; Value2: 0.1W; SizeArea_mm2: 1.28; AEC Qualified: N; VDC_V: 75V; AEC Category: Q200; SizeAreaWB_mm2: 4.68
R43 = CMP-0025686-1: RES, 10.0 k, 0.1%, 0.1 W, AEC-Q200 Grade 1, 0603; Manufacturer: Vishay-Dale; Power_W: 100mW; TempCo: 25 ppm/C; Value_Code: 10k0; U/M: EA; Value: 10.0k; EIA_Code: E192; Res_ohm: 10k; SizeX_mm: 1.6; SizeY_mm: 0.85; SizeZ_mm: 0.55; Value2: 0.1W; SizeArea_mm2: 1.36; AEC Qualified: Y; VDC_V: 75V; AEC Grade: 1; AEC Category: Q200
RT1 = CMP-0123214-2: ±1% tolerance 10kΩ linear thermistor available in 0402 and 0603 package options 2-X1SON -40 to 125; Manufacturer: Texas Instruments; Value: 10k; SizeZ_mm: 0.5mm; AEC Qualified: No; Standoff Height: 0mm; TaMax_C: +125°C; TaMin_C: -40°C; TJmax_C: +155°C; VDC_V: 5.5V; AEC Category: Q200; CompType: IC
TP1 TP2 = CMP-0055150-2: Test Point, Multipurpose, Orange, TH; Manufacturer: Keystone Electronics; CNHeader: FALSE; Green_Lifecycle: Active; Green_REACh: Passed; ContactFinish: Silver; CT: TRUE
TP3 = CMP-0055147-2: Test Point, Multipurpose, Red, TH; Manufacturer: Keystone Electronics; CNHeader: FALSE; Green_Lifecycle: Active; Green_REACh: Passed; ContactFinish: Silver; CT: TRUE
TP4 TP7 = CMP-0055138-2: Test Point, Miniature, Black, TH; Manufacturer: Keystone Electronics; CNHeader: FALSE; Green_Lifecycle: Active; Green_REACh: Passed; ContactFinish: Silver; CT: TRUE
TP5 = CMP-0055149-2: Test Point, Multipurpose, White, TH; Manufacturer: Keystone Electronics; CNHeader: FALSE; Green_Lifecycle: Active; Green_REACh: Passed; ContactFinish: Silver; CT: TRUE
TP6 = CMP-0055159-2: Test Point, Multipurpose, Grey, TH; Manufacturer: Keystone Electronics; CNHeader: FALSE; Green_Lifecycle: Active; Green_REACh: Passed; ContactFinish: Silver; CT: TRUE
TP8 = CMP-0055148-2: Test Point, Multipurpose, Black, TH; Manufacturer: Keystone Electronics; CNHeader: FALSE; Green_Lifecycle: Active; Green_REACh: Passed; ContactFinish: Silver; CT: TRUE
TP9-TP13 = CMP-0055141-2: Test Point, Miniature, Yellow, TH; Manufacturer: Keystone Electronics; CNHeader: FALSE; Green_Lifecycle: Active; Green_REACh: Passed; ContactFinish: Silver; CT: TRUE
U1 = CMP-0123255-3: 55V 4-Switch Buck-Boost Controller with I2C interface; Manufacturer: Texas Instruments; SizeZ_mm: 1mm; AEC Qualified: No; Min Supply Voltage: 3.5V; Nominal Supply Current: 65uA; Number Of Outputs: 1; Output Type: AdjustableProgrammable; Output Voltage: 1-55V; Standoff Height: 0mm; Switching Frequency: 100-2200kHz; Switching Topology: Boost,Buck,Buck-Boost; TJmax_C: +150°C; AEC Category: Q200; CompType: IC

## Sheet SR135B_Hardware.SchDoc: LM51772RWE EVM Hardware
size 431 x 279 mm; Date: Not shown in title block; ApprovedBy: Not shown in title block; CheckedBy: Not shown in title block; Author: Not shown in title block; CompanyName: Not shown in title block; Engineer: Not shown in title block; Organization: Not shown in title block; Address1: Not shown in title block; Address2: Not shown in title block; Address3: Not shown in title block; Address4: Not shown in title block; DocumentNumber: 2; Revision: Use project parameter SCH_Rev; SheetNumber: 2; SheetTotal: 2; PageSetup: Record=PageOptions¦CenterHorizontal=True¦CenterVertical=True¦PrintScale=1.00¦XCorrection=1.00¦YCorrection=1.00¦PrintKind=0¦BorderSize=5000000¦LeftOffset=0¦BottomOffset=0¦Orientation=2¦PaperLength=1000¦PaperWidth=1000¦Scale=100¦PaperSource=15¦PrintQuality=600¦MediaType=1¦DitherType=10¦PaperKind=Letter¦PrintScaleMode=1
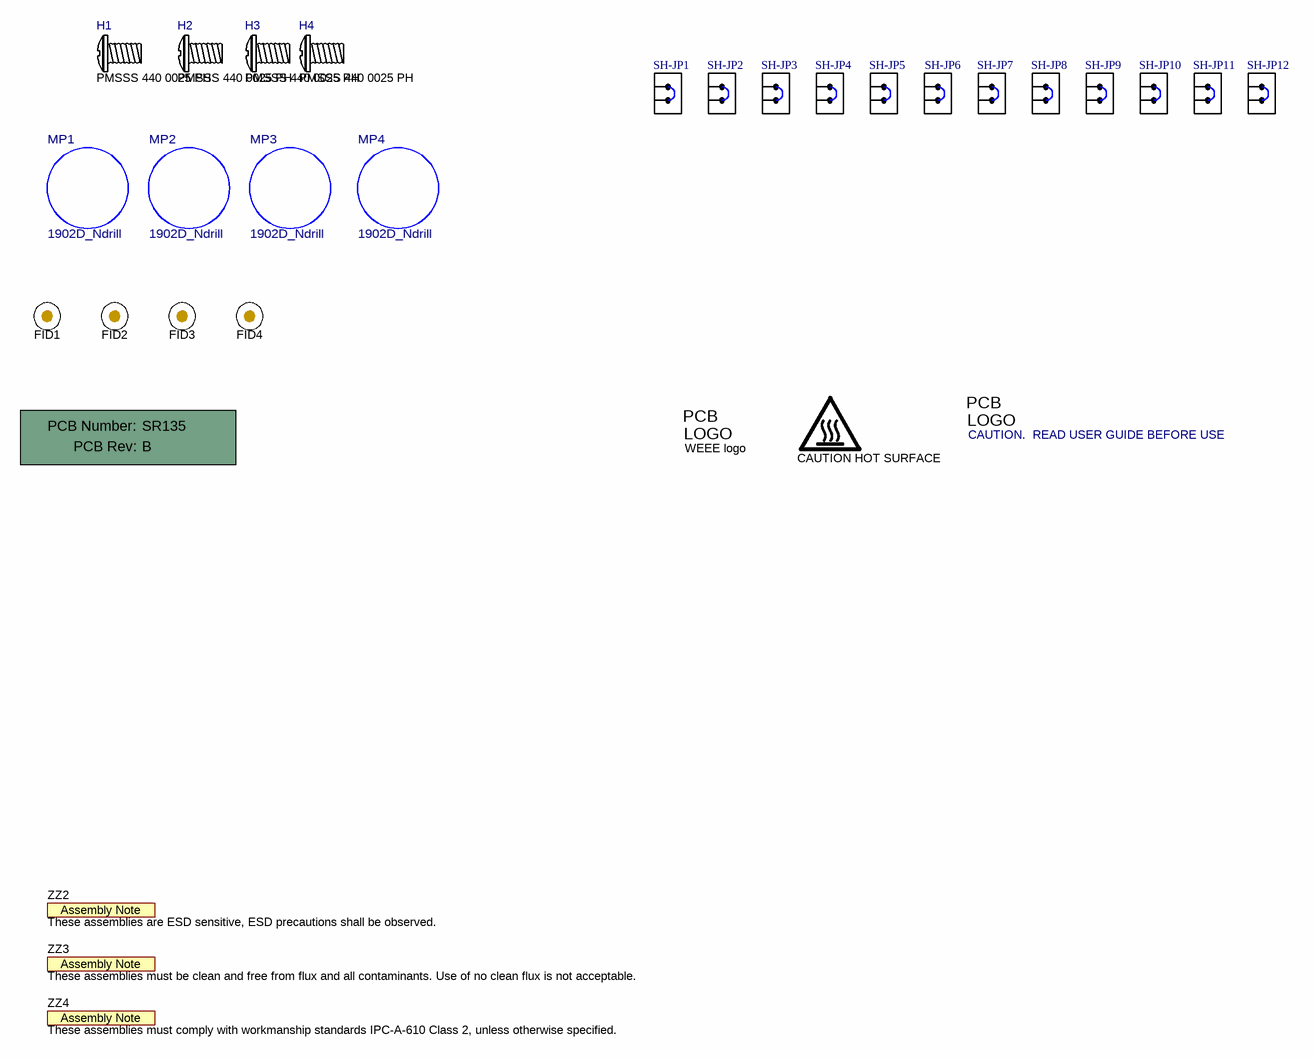
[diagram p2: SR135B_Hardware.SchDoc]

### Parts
!PCB  Printed Circuit Board  (value not drawn)  (mechanical)
FID1  Fiducial  [Fiducial10-20]  (value not drawn)
FID2  Fiducial  [Fiducial10-20]  (value not drawn)
FID3  Fiducial  [Fiducial10-20]  (value not drawn)
FID4  Fiducial  [Fiducial10-20]  (value not drawn)
H1  PMSSS 440 0025 PH  [B_F_PMSSS4400025PH]
H2  PMSSS 440 0025 PH  [B_F_PMSSS4400025PH]
H3  PMSSS 440 0025 PH  [B_F_PMSSS4400025PH]
H4  PMSSS 440 0025 PH  [B_F_PMSSS4400025PH]
Logo4  WEEE logo  [WEEE_Minimum]  (no BOM)
Logo5  CAUTION HOT SURFACE  [IEC_HotSurface_Small]  (no BOM)
Logo6  CAUTION.  READ USER GUIDE BEFORE USE  [IEC_Caution_Small]  (no BOM)
MP1  1902D_Ndrill  [FP-1902D_Ndrill_HEX_STANDOFF-MFG]
MP2  1902D_Ndrill  [FP-1902D_Ndrill_HEX_STANDOFF-MFG]
MP3  1902D_Ndrill  [FP-1902D_Ndrill_HEX_STANDOFF-MFG]
MP4  1902D_Ndrill  [FP-1902D_Ndrill_HEX_STANDOFF-MFG]
SH-JP1  M7582-05  [Harwin_M7582-05]  (value not drawn)
SH-JP2  M7582-05  [Harwin_M7582-05]  (value not drawn)
SH-JP3  M7582-05  [Harwin_M7582-05]  (value not drawn)
SH-JP4  M7582-05  [Harwin_M7582-05]  (value not drawn)
SH-JP5  M7582-05  [Harwin_M7582-05]  (value not drawn)
SH-JP6  M7582-05  [Harwin_M7582-05]  (value not drawn)
SH-JP7  M7582-05  [Harwin_M7582-05]  (value not drawn)
SH-JP8  M7582-05  [Harwin_M7582-05]  (value not drawn)
SH-JP9  M7582-05  [Harwin_M7582-05]  (value not drawn)
SH-JP10  M7582-05  [Harwin_M7582-05]  (value not drawn)
SH-JP11  M7582-05  [Harwin_M7582-05]  (value not drawn)
SH-JP12  M7582-05  [Harwin_M7582-05]  (value not drawn)
ZZ2  These assemblies are ESD sensitive, ESD precautions shall be observed.  [AssemblyNote]  (no BOM)
ZZ3  These assemblies must be clean and free from flux and all contaminants. Use of no clean flux is not acceptable.  [AssemblyNote]  (no BOM)
ZZ4  These assemblies must comply with workmanship standards IPC-A-610 Class 2, unless otherwise specified.  [AssemblyNote]  (no BOM)

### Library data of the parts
!PCB = CMP-0003618-2: Manufacturer: Any; PartNumber: SR135
FID1-FID4 = CMP-0077181-1: Fiducial mark.  There is nothing to buy or mount.
H1-H4 = CMP-0003715-1: MACHINE SCREW PAN PHILLIPS 4-40; Manufacturer: B&F Fastener Supply; CompType: Standoff
Logo4 = CMP-0074769-4: Manufacturer: Texas Instruments; CompType: IC; AEC Category: Q200
Logo5 = CMP-0074837-2: IEC 61010-1 Hot Surface Warning; Manufacturer: Texas Instruments; SymbolCreator: a0412235; CompType: IC; AEC Category: Q200
Logo6 = CMP-0074836-1: IEC 61010-1 Caution Warning; SymbolCreator: a0412235; Lib Reference: IEC_Caution
MP1-MP4 = CMP-0090542-1: Hex Standoff Threaded #4-40 Nylon 0.750" (19.05mm) 3/4" Natural; Manufacturer: Keystone Electronics; AEC Qualified: No; SizeZ_mm: 19.43mm
SH-JP1-SH-JP12 = CMP-0078738-1: Single Operation 2.54mm Pitch Open Top Jumper Socket; Manufacturer: Harwin
ZZ2 = CMP-0077236-1
ZZ3 = CMP-0077237-1
ZZ4 = CMP-0077238-1

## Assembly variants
001: not fitted C35 D2 Q2 Q3 R5 R8 R11 R12 R19 R30 R36 R38 R39 R40 R41 R42 SH-JP2 SH-JP3 SH-JP4 SH-JP6 SH-JP7 SH-JP8 SH-JP10 SH-JP11 SH-JP12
